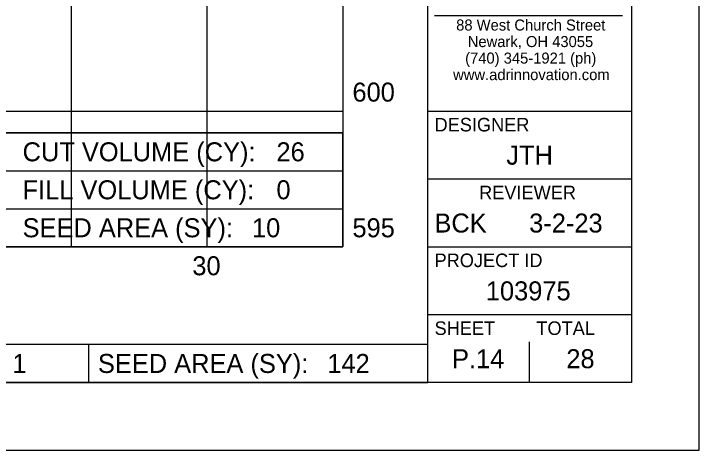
# Model space of a CAD drawing. Extents: x 0 to 170, y 0 to 110.
# Drawn here: x 144.75 to 170, y 0 to 16.09 of the extents above; entities that cross this region are included whole.
import ezdxf

# ---------------------------------------------------------------- set-up
doc = ezdxf.new("R2010")
doc.units = 0
for name, color, linetype in [('SH_Border', 7, 'Continuous'), ('SH_Cut_Line', 7, 'Continuous'), ('SH_Data', 7, 'Continuous'), ('SH_Major_Grid_Line', 7, 'Continuous'), ('SH_Masking', 7, 'Continuous')]:
    doc.layers.add(name, color=color, linetype=linetype)

msp = doc.modelspace()

# ---------------------------------------------------------------- linework, layer by layer
at = {"layer": 'SH_Border'}
for p, q in [((160, 2.5), (160, 107.5)), ((160, 12.5), (167.5, 12.5)), ((160, 10), (167.5, 10)), ((160, 7.5), (167.5, 7.5)), ((160, 5), (167.5, 5))]:
    msp.add_line(p, q, dxfattribs=at)
msp.add_lwpolyline([(7.5, 107.5), (167.5, 107.5), (167.5, 2.5), (7.5, 2.5)], close=True, dxfattribs=at)
at = {"layer": 'SH_Cut_Line'}
msp.add_lwpolyline([(0, 0), (170, 0), (170, 110), (0, 110)], close=True, dxfattribs=at)
at = {"layer": 'SH_Data'}
for p, q in [((160.242, 16.024), (167.166, 16.024)), ((132.875, 10.3), (156.875, 10.3)), ((132.875, 8.9), (156.875, 8.9)), ((147.5, 3.9), (147.5, 2.5)), ((163.75, 2.5), (163.75, 4)), ((161.875, 3.375), (161.875, 3.375))]:
    msp.add_line(p, q, dxfattribs=at)
for points in [[(86.875, 27.5), (156.875, 27.5), (156.875, 7.5), (86.875, 7.5)], [(132.875, 7.5), (156.875, 7.5), (156.875, 11.7), (132.875, 11.7)], [(101, 2.5), (160, 2.5), (160, 3.9), (101, 3.9)]]:
    msp.add_lwpolyline(points, close=True, dxfattribs=at)
at = {"layer": 'SH_Major_Grid_Line'}
for p, q in [((146.875, 7.5), (146.875, 27.5)), ((151.875, 7.5), (151.875, 27.5)), ((86.875, 12.5), (156.875, 12.5))]:
    msp.add_line(p, q, dxfattribs=at)
at = {"layer": 'SH_Masking'}
msp.add_lwpolyline([(132.875, 11.7), (156.875, 11.7), (156.875, 7.5), (132.875, 7.5)], close=True, dxfattribs=at)

# ---------------------------------------------------------------- texts
at = {"layer": 'SH_Data'}
for s, height, p in [('88 West Church Street', 0.40625, (161.045, 15.469)), ('Newark, OH 43055', 0.40625, (161.472, 14.859)), ('(740) 345-1921 (ph)', 0.40625, (161.376, 14.25)), ('www.adrinnovation.com', 0.40625, (160.932, 13.641)), ('600', 0.7, (157.225, 12.85)), ('DESIGNER', 0.5, (160.25, 11.75)), ('CUT VOLUME (CY):', 0.7, (145.075, 10.65)), ('26', 0.7, (154.425, 10.65)), ('JTH', 0.7, (162.893, 10.525)), ('FILL VOLUME (CY):', 0.7, (145.075, 9.25)), ('0', 0.7, (154.425, 9.25)), ('REVIEWER', 0.5, (161.891, 9.25)), ('SEED AREA (SY):', 0.7, (145.075, 7.85)), ('BCK', 0.7, (160.245, 8.025)), ('3-2-23', 0.7, (163.734, 8.025)), ('10', 0.7, (153.525, 7.85)), ('595', 0.7, (157.225, 7.85)), ('30', 0.7, (151.327, 6.45)), ('PROJECT ID', 0.5, (160.25, 6.75)), ('103975', 0.7, (162.138, 5.525)), ('SHEET', 0.5, (160.25, 4.25)), ('TOTAL', 0.5, (164, 4.25)), ('1', 0.7, (144.7, 2.85)), ('SEED AREA (SY):', 0.7, (147.85, 2.85)), ('142', 0.7, (156.3, 2.85)), ('P.14', 0.7, (160.893, 3.025)), ('28', 0.7, (165.103, 3.025))]:
    msp.add_text(s, height=height, dxfattribs=at).set_placement(p)

doc.saveas('drawing.dxf')
